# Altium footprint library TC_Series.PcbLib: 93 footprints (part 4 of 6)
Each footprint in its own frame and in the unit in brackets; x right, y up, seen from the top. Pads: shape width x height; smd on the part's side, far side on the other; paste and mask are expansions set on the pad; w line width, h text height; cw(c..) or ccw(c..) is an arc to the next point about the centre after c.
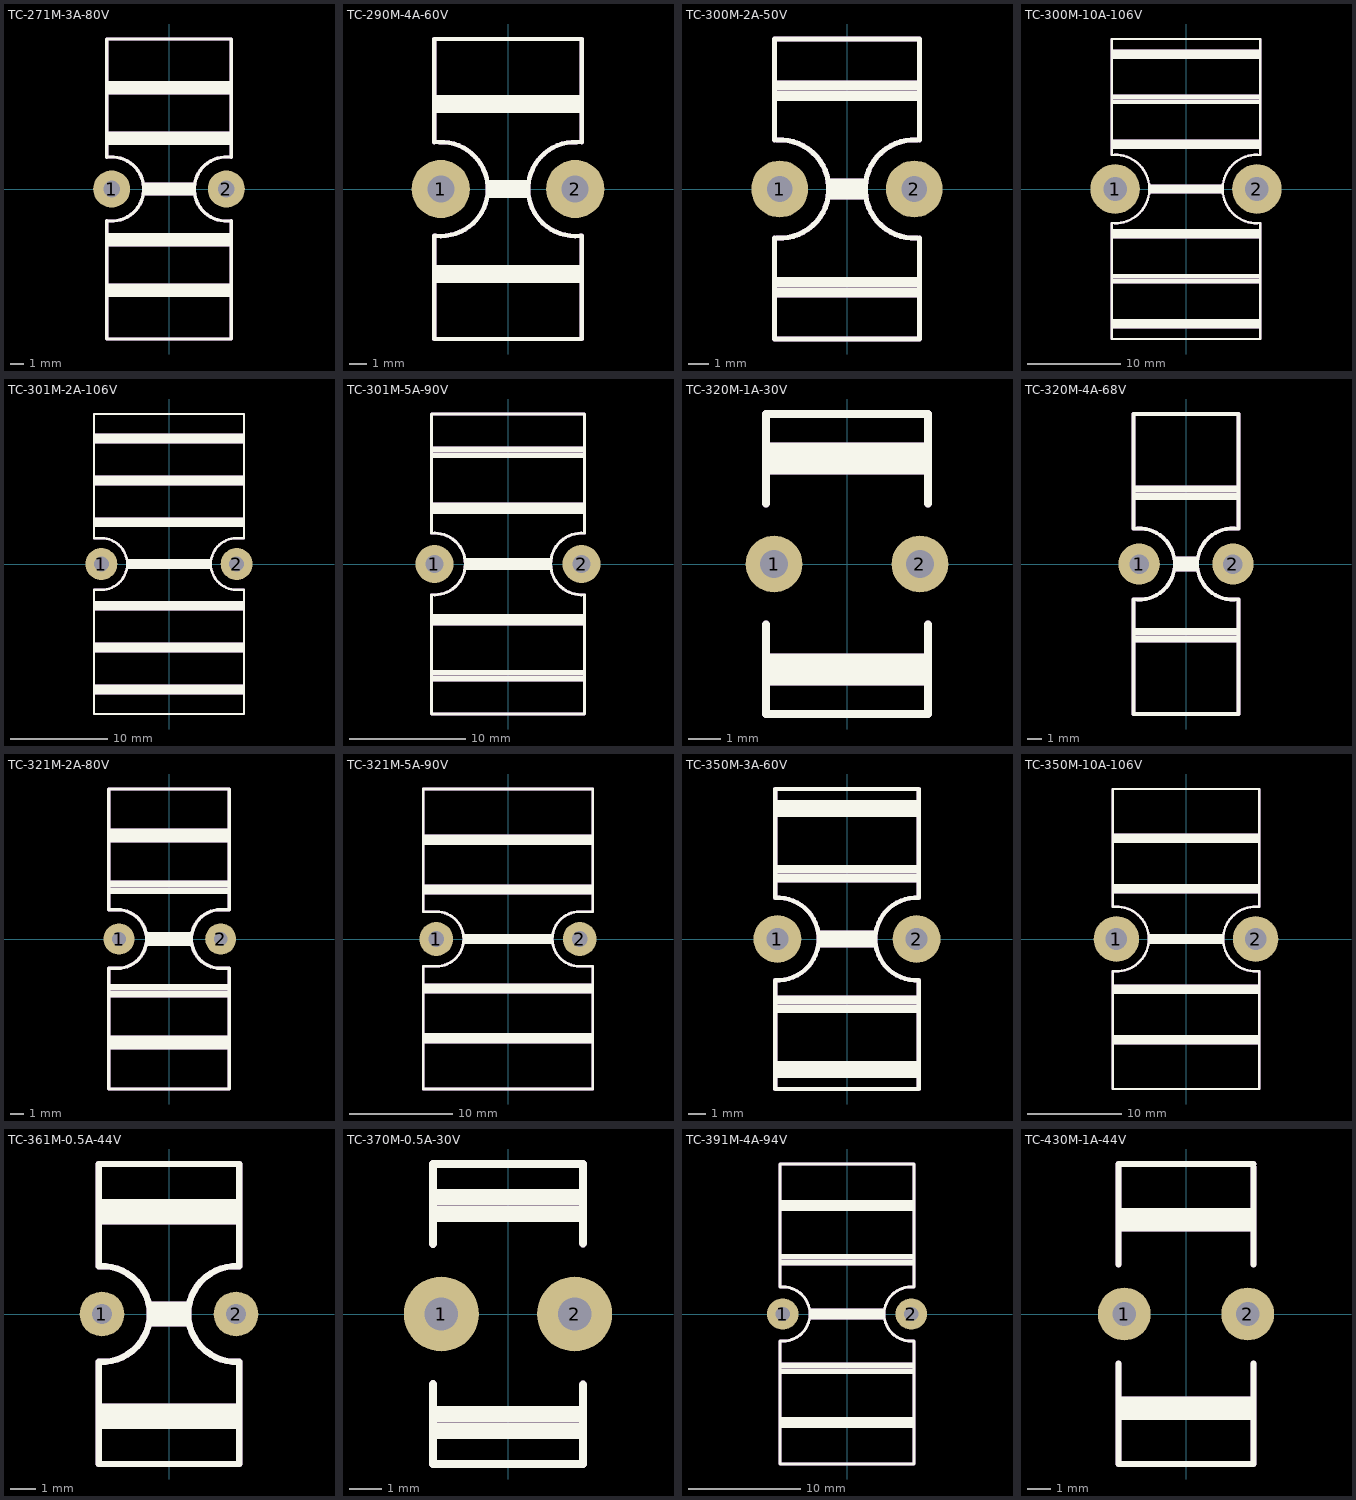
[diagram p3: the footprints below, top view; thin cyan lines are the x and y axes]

## TC-271M-3A-80V [mil]
pads (2):
  round 110 hole 50: 1(-170,0) 2(170,0)
Top Overlay:
  lines w10: -185,-93.84 -185,-445 185,-445 185,-93.84 ; -185,93.84 -185,445 185,445 185,93.84 ; -184.82,-93.84 ccw(c-170,0) -184.82,93.84 ; 184.82,-93.84 cw(c170,0) 184.82,93.84
  lines w19.68: -180,-310 180,-310 ; -180,-290 180,-290 ; -180,-160 180,-160 ; -180,-140 180,-140 ; -180,140 180,140 ; -180,160 180,160 ; -180,290 180,290 ; -180,310 180,310 ; -70,-10 70,-10 ; -70,10 70,10
Mechanical 29:
  lines w10: -185,-93.84 -185,-445 185,-445 185,-93.84 ; -185,93.84 -185,445 185,445 185,93.84 ; -184.82,-93.84 ccw(c-170,0) -184.82,93.84 ; 184.82,-93.84 cw(c170,0) 184.82,93.84
  lines w19.68: -180,-310 180,-310 ; -180,-290 180,-290 ; -180,-160 180,-160 ; -180,-140 180,-140 ; -180,140 180,140 ; -180,160 180,160 ; -180,290 180,290 ; -180,310 180,310 ; -70,-10 70,-10 ; -70,10 70,10
  text "'.Designator'" at -1750,-64.85 h400

## TC-290M-4A-60V [mil]
pads (2):
  round 130 hole 60: 1(-150,0) 2(150,0)
Top Overlay:
  lines w10: -165,-103.94 -165,-335 165,-335 165,-103.94 ; -165,103.94 -165,335 165,335 165,103.94 ; -164.85,103.94 cw(c-150,0) -160.99,-104.42 ; 160.99,-104.42 cw(c150,0) 164.85,103.94
  lines w19.68: -160,-200 160,-200 ; -160,-180 160,-180 ; -160,180 160,180 ; -160,200 160,200 ; -40,-10 40,-10 ; -40,10 40,10
Mechanical 29:
  lines w10: -165,-103.94 -165,-335 165,-335 165,-103.94 ; -165,103.94 -165,335 165,335 165,103.94 ; -164.85,103.94 cw(c-150,0) -160.99,-104.42 ; 160.99,-104.42 cw(c150,0) 164.85,103.94
  lines w19.68: -160,-200 160,-200 ; -160,-180 160,-180 ; -160,180 160,180 ; -160,200 160,200 ; -40,-10 40,-10 ; -40,10 40,10
  text "'.Designator'" at -1750,-64.85 h400

## TC-300M-2A-50V [mil]
pads (2):
  round 110 hole 50: 1(-130,0) 2(130,0)
Top Overlay:
  lines w10: -140,-94.87 -140,-290 140,-290 140,-95 ; -140,94.87 -140,290 140,290 140,95 ; -134.99,-94.87 ccw(c-130,0) -134.99,94.87 ; 134.99,-94.87 cw(c130,0) 134.99,94.87
  lines w19.68: -135,-200 135,-200 ; -135,-180 135,-180 ; -135,180 135,180 ; -135,200 135,200 ; -30,-10 30,-10 ; -30,10 30,10
Mechanical 29:
  lines w10: -140,-94.87 -140,-290 140,-290 140,-95 ; -140,94.87 -140,290 140,290 140,95 ; -134.99,-94.87 ccw(c-130,0) -134.99,94.87 ; 134.99,-94.87 cw(c130,0) 134.99,94.87
  lines w19.68: -135,-200 135,-200 ; -135,-180 135,-180 ; -135,180 135,180 ; -135,200 135,200 ; -30,-10 30,-10 ; -30,10 30,10
  text "'.Designator'" at -1750,-64.85 h400

## TC-300M-10A-106V [mil]
pads (2):
  round 210 hole 100: 1(-300,0) 2(300,0)
Top Overlay:
  lines w10: -315,-145 -315,-635 315,-635 315,-144.23 ; -315,144.23 -315,635 315,635 315,144.23 ; -314.92,-144.23 ccw(c-300,0) -314.92,144.23 ; 314.92,-144.23 cw(c300,0) 314.92,144.23
  lines w19.68: -310,-580 310,-580 ; -310,-560 310,-560 ; -310,-390 310,-390 ; -310,-370 310,-370 ; -310,-200 310,-200 ; -310,-180 310,-180 ; -310,180 310,180 ; -310,200 310,200 ; -310,370 310,370 ; -310,390 310,390 ; -310,560 310,560 ; -310,580 310,580 ; -150,-10 150,-10 ; -150,10 150,10
Mechanical 29:
  lines w10: -315,-145 -315,-635 315,-635 315,-144.23 ; -315,144.23 -315,635 315,635 315,144.23 ; -314.92,-144.23 ccw(c-300,0) -314.92,144.23 ; 314.92,-144.23 cw(c300,0) 314.92,144.23
  lines w19.68: -310,-580 310,-580 ; -310,-560 310,-560 ; -310,-390 310,-390 ; -310,-370 310,-370 ; -310,-200 310,-200 ; -310,-180 310,-180 ; -310,180 310,180 ; -310,200 310,200 ; -310,370 310,370 ; -310,390 310,390 ; -310,560 310,560 ; -310,580 310,580 ; -150,-10 150,-10 ; -150,10 150,10
  text "'.Designator'" at -1750,-64.85 h400

## TC-301M-2A-106V [mil]
pads (2):
  round 130 hole 60: 1(-275,0) 2(275,0)
Top Overlay:
  lines w10: -305,-104.53 -305,-610 305,-610 305,-104.53 ; -305,104.53 -305,610 305,610 305,104.53 ; -304.53,-105 -275,-105 ccw(c-275,0) -275,105 -304.53,105 ; 304.53,-105 275,-105 cw(c275,0) 275,105 304.53,105
  lines w19.68: -300,-520 300,-520 ; -300,-500 300,-500 ; -300,-350 300,-350 ; -300,-330 300,-330 ; -300,-180 300,-180 ; -300,-160 300,-160 ; -300,160 300,160 ; -300,180 300,180 ; -300,330 300,330 ; -300,350 300,350 ; -300,500 300,500 ; -300,520 300,520 ; -165,-10 165,-10 ; -165,10 165,10
Mechanical 29:
  lines w10: -305,-104.53 -305,-610 305,-610 305,-104.53 ; -305,104.53 -305,610 305,610 305,104.53 ; -304.53,-105 -275,-105 ccw(c-275,0) -275,105 -304.53,105 ; 304.53,-105 275,-105 cw(c275,0) 275,105 304.53,105
  lines w19.68: -300,-520 300,-520 ; -300,-500 300,-500 ; -300,-350 300,-350 ; -300,-330 300,-330 ; -300,-180 300,-180 ; -300,-160 300,-160 ; -300,160 300,160 ; -300,180 300,180 ; -300,330 300,330 ; -300,350 300,350 ; -300,500 300,500 ; -300,520 300,520 ; -165,-10 165,-10 ; -165,10 165,10
  text "'.Designator'" at -1750,-64.85 h400

## TC-301M-5A-90V [mil]
pads (2):
  round 130 hole 60: 1(-250,0) 2(250,0)
Top Overlay:
  lines w10: -260,-104.57 -260,-510 260,-510 260,-104.53 ; -260,-104.52 ccw(c-250,0) -259.95,104.53 ; -260,104.53 -260,510 260,510 260,104.53 ; 259.95,104.53 ccw(c250,0) 260,-104.52
  lines w19.68: -255,-390 255,-390 ; -255,-370 255,-370 ; -255,-200 255,-200 ; -255,-180 255,-180 ; -255,180 255,180 ; -255,200 255,200 ; -255,370 255,370 ; -255,390 255,390 ; -140,-10 140,-10 ; -140,10 140,10
Mechanical 29:
  lines w10: -260,-104.57 -260,-510 260,-510 260,-104.53 ; -260,-104.52 ccw(c-250,0) -259.95,104.53 ; -260,104.53 -260,510 260,510 260,104.53 ; 259.95,104.53 ccw(c250,0) 260,-104.52
  lines w19.68: -255,-390 255,-390 ; -255,-370 255,-370 ; -255,-200 255,-200 ; -255,-180 255,-180 ; -255,180 255,180 ; -255,200 255,200 ; -255,370 255,370 ; -255,390 255,390 ; -140,-10 140,-10 ; -140,10 140,10
  text "'.Designator'" at -1750,-64.85 h400

## TC-320M-1A-30V [mil]
pads (2):
  round 70 hole 34: 1(-90,0) 2(90,0)
Top Overlay:
  lines w10: -100,-74.78 -100,-185 100,-185 100,-74.78 ; -100,74.78 -100,185 100,185 100,74.78
  lines w19.68: -95,-140 95,-140 ; -95,-120 95,-120 ; -95,120 95,120 ; -95,140 95,140
Mechanical 29:
  lines w10: -100,-74.78 -100,-185 100,-185 100,-74.78 ; -100,74.78 -100,185 100,185 100,74.78
  lines w19.68: -95,-140 95,-140 ; -95,-120 95,-120 ; -95,120 95,120 ; -95,140 95,140
  text "'.Designator'" at -785,-37.45 h200

## TC-320M-4A-68V [mil]
pads (2):
  round 110 hole 52: 1(-125,0) 2(125,0)
Top Overlay:
  lines w10: -140,-94.34 -140,-400 140,-400 140,-94.35 ; -140,94.35 -140,400 140,400 140,94.35 ; -139.92,-93.82 ccw(c-125,0) -139.92,93.82 ; 139.92,-93.82 cw(c125,0) 139.92,93.82
  lines w19.68: -135,-200 135,-200 ; -135,-180 135,-180 ; -135,180 135,180 ; -135,200 135,200 ; -25,-10 25,-10 ; -25,10 25,10
Mechanical 29:
  lines w10: -140,-94.34 -140,-400 140,-400 140,-94.35 ; -140,94.35 -140,400 140,400 140,94.35 ; -139.92,-93.82 ccw(c-125,0) -139.92,93.82 ; 139.92,-93.82 cw(c125,0) 139.92,93.82
  lines w19.68: -135,-200 135,-200 ; -135,-180 135,-180 ; -135,180 135,180 ; -135,200 135,200 ; -25,-10 25,-10 ; -25,10 25,10
  text "'.Designator'" at -1750,-64.85 h400

## TC-321M-2A-80V [mil]
pads (2):
  round 90 hole 40: 1(-145,0) 2(150,0)
Top Overlay:
  lines w10: -175,-435 -175,-85 -150,-85 ccw(c-150,0) -150,85 -175,85 -175,435 175,435 175,85 150,85 ccw(c150,0) 150,-85 175,-85 175,-435 -175,-435
  lines w19.68: -170,-310 170,-310 ; -170,-290 170,-290 ; -170,-160 170,-160 ; -170,-140 170,-140 ; -170,140 170,140 ; -170,160 170,160 ; -170,290 170,290 ; -170,310 170,310 ; -60,-10 60,-10 ; -60,10 60,10
Mechanical 29:
  lines w10: -175,-435 -175,-85 -150,-85 ccw(c-150,0) -150,85 -175,85 -175,435 175,435 175,85 150,85 ccw(c150,0) 150,-85 175,-85 175,-435 -175,-435
  lines w19.68: -170,-310 170,-310 ; -170,-290 170,-290 ; -170,-160 170,-160 ; -170,-140 170,-140 ; -170,140 170,140 ; -170,160 170,160 ; -170,290 170,290 ; -170,310 170,310 ; -60,-10 60,-10 ; -60,10 60,10
  text "'.Designator'" at -1750,-64.85 h400

## TC-321M-5A-90V [mil]
pads (2):
  round 130 hole 60: 1(-275,0) 2(275,0)
Top Overlay:
  lines w10: -325,-575 -325,-105 -275,-105 ccw(c-275,0) -275,105 -325,105 -325,575 325,575 325,105 275,105 ccw(c275,0) 275,-105 325,-105 325,-575 -325,-575
  lines w19.68: -320,-390 320,-390 ; -320,-370 320,-370 ; -320,-200 320,-200 ; -320,-180 320,-180 ; -320,180 320,180 ; -320,200 320,200 ; -320,370 320,370 ; -320,390 320,390 ; -165,-10 165,-10 ; -165,10 165,10
Mechanical 29:
  lines w10: -325,-575 -325,-105 -275,-105 ccw(c-275,0) -275,105 -325,105 -325,575 325,575 325,105 275,105 ccw(c275,0) 275,-105 325,-105 325,-575 -325,-575
  lines w19.68: -320,-390 320,-390 ; -320,-370 320,-370 ; -320,-200 320,-200 ; -320,-180 320,-180 ; -320,180 320,180 ; -320,200 320,200 ; -320,370 320,370 ; -320,390 320,390 ; -165,-10 165,-10 ; -165,10 165,10
  text "'.Designator'" at -1750,-64.85 h400

## TC-350M-3A-60V [mil]
pads (2):
  round 110 hole 50: 1(-160,0) 2(160,0)
Top Overlay:
  lines w10: -165,-94.87 ccw(c-160,0) -165,94.87 ; -165,-94.48 -165,-345 165,-345 165,-95 ; -165,94.48 -165,345 165,345 165,95 ; 164.99,-94.87 cw(c160,0) 164.99,94.87
  lines w19.68: -160,-310 160,-310 ; -160,-290 160,-290 ; -160,-160 160,-160 ; -160,-140 160,-140 ; -160,140 160,140 ; -160,160 160,160 ; -160,290 160,290 ; -160,310 160,310 ; -60,-10 60,-10 ; -60,10 60,10
Mechanical 29:
  lines w10: -165,-94.87 ccw(c-160,0) -165,94.87 ; -165,-94.48 -165,-345 165,-345 165,-95 ; -165,94.48 -165,345 165,345 165,95 ; 164.99,-94.87 cw(c160,0) 164.99,94.87
  lines w19.68: -160,-310 160,-310 ; -160,-290 160,-290 ; -160,-160 160,-160 ; -160,-140 160,-140 ; -160,140 160,140 ; -160,160 160,160 ; -160,290 160,290 ; -160,310 160,310 ; -60,-10 60,-10 ; -60,10 60,10
  text "'.Designator'" at -1750,-64.85 h400

## TC-350M-10A-106V [mil]
pads (2):
  round 190 hole 90: 1(-290,0) 2(290,0)
Top Overlay:
  lines w10: -305,134.17 -305,625 305,625 305,134.17 ; -304.91,134.17 cw(c-290,0) -305,-134.16 -305,-625 305,-625 305,-134.17 cw(c290,0) 304.91,134.17
  lines w19.68: -300,-430 300,-430 ; -300,-410 300,-410 ; -300,-220 300,-220 ; -300,-200 300,-200 ; -300,200 300,200 ; -300,220 300,220 ; -300,410 300,410 ; -300,430 300,430 ; -150,-10 150,-10 ; -150,10 150,10
Mechanical 29:
  lines w10: -305,134.17 -305,625 305,625 305,134.17 ; -304.91,134.17 cw(c-290,0) -305,-134.16 -305,-625 305,-625 305,-134.17 cw(c290,0) 304.91,134.17
  lines w19.68: -300,-430 300,-430 ; -300,-410 300,-410 ; -300,-220 300,-220 ; -300,-200 300,-200 ; -300,200 300,200 ; -300,220 300,220 ; -300,410 300,410 ; -300,430 300,430 ; -150,-10 150,-10 ; -150,10 150,10
  text "'.Designator'" at -1750,-64.85 h400

## TC-361M-0.5A-44V [mil]
pads (2):
  round 70 hole 32: 1(-105,0) 2(105,0)
Top Overlay:
  lines w10: -110,-74.87 -110,-235 110,-235 ; -110,74.87 -110,235 110,235 ; -109.4,-74.87 ccw(c-105,0) -109.4,74.87 ; 109.4,-74.87 cw(c105,0) 109.41,74.87 ; 110,-234.83 110,-74.87 ; 110,74.87 110,234.83
  lines w19.68: -105,-170 105,-170 ; -105,-150 105,-150 ; -105,150 105,150 ; -105,170 105,170 ; -25,-10 25,-10 ; -25,10 25,10
Mechanical 29:
  lines w10: -110,-74.87 -110,-235 110,-235 ; -110,74.87 -110,235 110,235 ; -109.4,-74.87 ccw(c-105,0) -109.4,74.87 ; 109.4,-74.87 cw(c105,0) 109.41,74.87 ; 110,-234.83 110,-74.87 ; 110,74.87 110,234.83
  lines w19.68: -105,-170 105,-170 ; -105,-150 105,-150 ; -105,150 105,150 ; -105,170 105,170 ; -25,-10 25,-10 ; -25,10 25,10
  text "'.Designator'" at -1750,-64.85 h400

## TC-370M-0.5A-30V [mil]
pads (2):
  round 90 hole 40: 1(-80,0) 2(80,0)
Top Overlay:
  lines w10: -90,-84.42 -90,-180 90,-180 90,-85 ; -90,84.42 -90,180 90,180 90,85
  lines w19.68: -85,-140 85,-140 ; -85,-120 85,-120 ; -85,120 85,120 ; -85,140 85,140
Mechanical 29:
  lines w10: -90,-84.42 -90,-180 90,-180 90,-85 ; -90,84.42 -90,180 90,180 90,85
  lines w19.68: -85,-140 85,-140 ; -85,-120 85,-120 ; -85,120 85,120 ; -85,140 85,140
  text "'.Designator'" at -880,-42.45 h200

## TC-391M-4A-94V [mil]
pads (2):
  round 110 hole 50: 1(-225,0) 2(225,0)
Top Overlay:
  lines w10: -235,-94.48 -235,-525 235,-525 235,-94.48 ; -235,94.48 -235,525 235,525 235,94.48 ; -234.95,-94.48 ccw(c-225,0) -234.95,94.48 ; 234.95,-94.48 cw(c225,0) 234.95,94.48
  lines w19.68: -230,-390 230,-390 ; -230,-370 230,-370 ; -230,-200 230,-200 ; -230,-180 230,-180 ; -230,180 230,180 ; -230,200 230,200 ; -230,370 230,370 ; -230,390 230,390 ; -125,-10 125,-10 ; -125,10 125,10
Mechanical 29:
  lines w10: -235,-94.48 -235,-525 235,-525 235,-94.48 ; -235,94.48 -235,525 235,525 235,94.48 ; -234.95,-94.48 ccw(c-225,0) -234.95,94.48 ; 234.95,-94.48 cw(c225,0) 234.95,94.48
  lines w19.68: -230,-390 230,-390 ; -230,-370 230,-370 ; -230,-200 230,-200 ; -230,-180 230,-180 ; -230,180 230,180 ; -230,200 230,200 ; -230,370 230,370 ; -230,390 230,390 ; -125,-10 125,-10 ; -125,10 125,10
  text "'.Designator'" at -1750,-64.85 h400

## TC-430M-1A-44V [mil]
pads (2):
  round 90 hole 40: 1(-105,0) 2(105,0)
Top Overlay:
  lines w10: -115,-84.42 -115,-255 115,-255 115,-84.42 ; -115,84.42 -115,255 115,255 ; 115,84.42 115,250
  lines w19.68: -110,-170 110,-170 ; -110,-150 110,-150 ; -110,150 110,150 ; -110,170 110,170
Mechanical 29:
  lines w10: -115,-84.42 -115,-255 115,-255 115,-84.42 ; -115,84.42 -115,255 115,255 ; 115,84.42 115,250
  lines w19.68: -110,-170 110,-170 ; -110,-150 110,-150 ; -110,150 110,150 ; -110,170 110,170
  text "'.Designator'" at -1750,-64.85 h400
